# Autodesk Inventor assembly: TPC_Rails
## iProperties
Shininess: 64.0
Length Units: 11272
Angle Units: 11279
Time Units: 11290
Mass Units: 11286
Length Display Precision: 3
Angle Display Precision: 2
Compacted: True
Part Number: TPC_Rails
Document SubType Name: Assembly
Created: 2004-08
Designer: Lori
Manufacturer: Standard
Standards Organization: Custom
Density: 0.0
Volumn: 0.0
Area: 0.0
PropertySet Name: Model Information
Control State: 0
Master: False
Checked Out: False
Author: Lori
